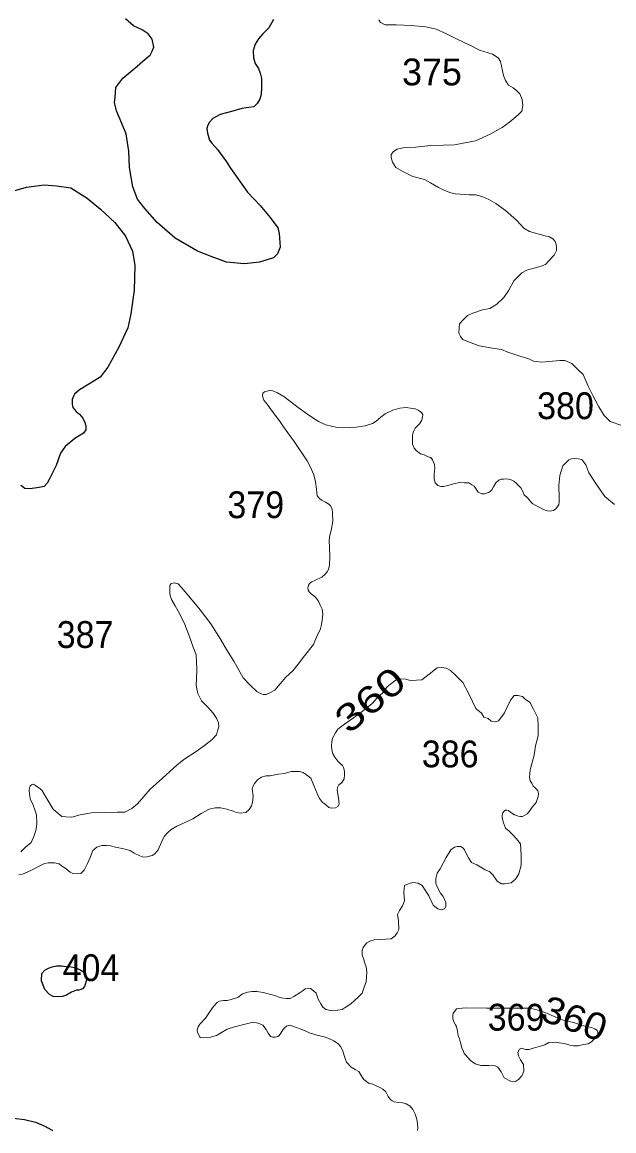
# Model space of a CAD drawing. Extents: x 445.4 to 500, y 8728.7 to 8784.
# Drawn here: x 478.95 to 482.49, y 8728.71 to 8735.33 of the extents above; entities that cross this region are included whole.
import ezdxf
from ezdxf.enums import TextEntityAlignment as Align

# ---------------------------------------------------------------- set-up
doc = ezdxf.new("R2010")
doc.units = 0
doc.header["$LTSCALE"] = 0.064
doc.layers.add('1', color=7, linetype='Continuous', lineweight=25)
doc.layers.add('2', color=7, linetype='Continuous', lineweight=13)
doc.layers.add('21', color=7, linetype='Continuous')
doc.layers.add('61', color=7, linetype='Continuous')

msp = doc.modelspace()

# ---------------------------------------------------------------- linework, layer by layer
at = {"layer": '1'}
for points in [[(480.4553, 8735.3481), (480.4282, 8735.2982), (480.3931, 8735.2632), (480.3661, 8735.2335), (480.3471, 8735.2012), (480.3336, 8735.1634), (480.3363, 8735.1203), (480.3471, 8735.0853), (480.3661, 8735.0556), (480.3769, 8735.0287), (480.385, 8734.9963), (480.385, 8734.9424), (480.3823, 8734.9006), (480.3742, 8734.8736), (480.358, 8734.8467), (480.3391, 8734.8278), (480.3094, 8734.8224), (480.2662, 8734.817), (480.2122, 8734.8008), (480.1366, 8734.782), (480.0934, 8734.7577), (480.0745, 8734.7362), (480.0637, 8734.7173), (480.0583, 8734.6984), (480.061, 8734.6688), (480.0745, 8734.6283), (480.088, 8734.6095), (480.1204, 8734.5717), (480.1744, 8734.4989), (480.1987, 8734.4612), (480.3012, 8734.3168), (480.3768, 8734.2386), (480.4362, 8734.1658), (480.4824, 8734.1051), (480.4905, 8734.07), (480.4932, 8734.0161), (480.4959, 8733.9891), (480.4797, 8733.9487), (480.4554, 8733.9245), (480.3717, 8733.9002), (480.2825, 8733.8894), (480.1745, 8733.9002), (480.0827, 8733.9325), (480.0017, 8733.9649), (479.869, 8734.0437), (479.7603, 8734.1361), (479.6879, 8734.2204), (479.6436, 8734.2766), (479.6154, 8734.3489), (479.5953, 8734.4654), (479.5913, 8734.5618), (479.5752, 8734.6662), (479.5189, 8734.8028), (479.5067, 8734.8537), (479.5107, 8734.8818), (479.5147, 8734.942), (479.555, 8734.9983), (479.6274, 8735.0585), (479.7038, 8735.1228), (479.7199, 8735.1348), (479.732, 8735.1589), (479.7401, 8735.183), (479.732, 8735.2312), (479.7079, 8735.2633), (479.6716, 8735.2874), (479.6193, 8735.3115), (479.571, 8735.3517)], [(478.8634, 8734.313), (478.9804, 8734.3472), (479.086, 8734.3614), (479.1602, 8734.3557), (479.2458, 8734.3443), (479.3428, 8734.2817), (479.4227, 8734.2162), (479.5083, 8734.1365), (479.571, 8734.0539), (479.6138, 8733.9656), (479.6281, 8733.8802), (479.6231, 8733.7332), (479.6031, 8733.5909), (479.586, 8733.5083), (479.5318, 8733.3915), (479.4661, 8733.2733), (479.4205, 8733.2135), (479.3634, 8733.1765), (479.2978, 8733.1367), (479.2664, 8733.111), (479.2607, 8733.0996), (479.2521, 8733.0797), (479.2521, 8733.0512), (479.2578, 8733.0313), (479.2778, 8733.0085), (479.2978, 8732.9914), (479.3177, 8732.9686), (479.3292, 8732.943), (479.3349, 8732.9231), (479.3349, 8732.8974), (479.3205, 8732.8787), (479.2692, 8732.8474), (479.2121, 8732.7989), (479.1836, 8732.7591), (479.1579, 8732.685), (479.118, 8732.6053), (479.1037, 8732.5797), (479.0866, 8732.5597), (479.0552, 8732.554), (479.001, 8732.5455), (478.9696, 8732.5483), (478.9468, 8732.5654)], [(478.6614, 8728.7126), (478.6828, 8728.7538), (478.7229, 8728.7791), (478.7734, 8728.7917), (478.8218, 8728.7896), (478.9019, 8728.7875), (478.9692, 8728.7812), (479.0345, 8728.7644), (479.0851, 8728.7433), (479.1335, 8728.716), (479.1368, 8728.7129)]]:
    msp.add_lwpolyline(points, dxfattribs=at)
msp.add_lwpolyline([(479.2487, 8729.5402), (479.2147, 8729.5202), (479.1931, 8729.514), (479.1653, 8729.5125), (479.139, 8729.5156), (479.1174, 8729.5264), (479.0896, 8729.5572), (479.0696, 8729.6081), (479.0726, 8729.6512), (479.0896, 8729.6713), (479.1112, 8729.6836), (479.1344, 8729.6928), (479.1591, 8729.6975), (479.19, 8729.6975), (479.2163, 8729.6944), (479.2472, 8729.6913), (479.275, 8729.6851), (479.3043, 8729.6728), (479.3259, 8729.6574), (479.3367, 8729.6389), (479.3414, 8729.6173), (479.3259, 8729.5742), (479.3151, 8729.5603), (479.295, 8729.5526), (479.2796, 8729.5526), (479.2688, 8729.548)], close=True, dxfattribs=at)
at = {"layer": '2'}
for points in [[(481.0861, 8735.3455), (481.0955, 8735.3314), (481.1237, 8735.3173), (481.1895, 8735.3173), (481.2788, 8735.3126), (481.3657, 8735.3056), (481.4268, 8735.2915), (481.4902, 8735.2634), (481.5536, 8735.2306), (481.6288, 8735.1954), (481.6875, 8735.1649), (481.7651, 8735.1415), (481.7979, 8735.1204), (481.812, 8735.0969), (481.8308, 8735.0149), (481.8426, 8734.9844), (481.8594, 8734.9554), (481.8875, 8734.9413), (481.9087, 8734.9226), (481.9275, 8734.9038), (481.9416, 8734.871), (481.9463, 8734.8358), (481.9392, 8734.8006), (481.9181, 8734.7795), (481.8664, 8734.735), (481.8218, 8734.7045), (481.7513, 8734.6633), (481.662, 8734.6234), (481.5892, 8734.6094), (481.5375, 8734.6), (481.4717, 8734.5976), (481.3966, 8734.5953), (481.305, 8734.5859), (481.2392, 8734.5836), (481.1941, 8734.5736), (481.173, 8734.5595), (481.1589, 8734.5431), (481.1589, 8734.5244), (481.1659, 8734.4962), (481.1871, 8734.4657), (481.2293, 8734.4399), (481.2881, 8734.4118), (481.3585, 8734.393), (481.3933, 8734.3729), (481.4419, 8734.3452), (481.479, 8734.3267), (481.5161, 8734.3128), (481.5439, 8734.3082), (481.625, 8734.3012), (481.6667, 8734.3012), (481.7061, 8734.2897), (481.7432, 8734.2735), (481.7849, 8734.2503), (481.8428, 8734.2087), (481.9077, 8734.1509), (481.9517, 8734.1023), (481.9852, 8734.0828), (482.0709, 8734.0597), (482.1057, 8734.0505), (482.1242, 8734.0389), (482.1381, 8734.0227), (482.1474, 8733.9973), (482.1474, 8733.9695), (482.1335, 8733.9417), (482.0987, 8733.9047), (482.0802, 8733.8862)], [(482.0802, 8733.8862), (482.0547, 8733.8747), (482.0107, 8733.8631), (481.9689, 8733.8515), (481.9388, 8733.8354), (481.9156, 8733.8122), (481.8923, 8733.7877), (481.8622, 8733.7322), (481.8321, 8733.6883), (481.7904, 8733.6489), (481.7487, 8733.6235), (481.7046, 8733.6142), (481.6467, 8733.5957), (481.6142, 8733.5819), (481.5864, 8733.5541), (481.5679, 8733.531), (481.5656, 8733.5079), (481.5633, 8733.4755), (481.5725, 8733.4547), (481.5864, 8733.4385), (481.6212, 8733.4246), (481.6838, 8733.3991), (481.7649, 8733.3853), (481.8182, 8733.3783), (481.8553, 8733.3621), (481.9273, 8733.3379), (481.9806, 8733.3217), (482.0084, 8733.3078), (482.0571, 8733.3032), (482.1011, 8733.3055), (482.166, 8733.3124), (482.1962, 8733.3124), (482.2379, 8733.2939), (482.2749, 8733.2592), (482.3051, 8733.2291), (482.3352, 8733.1598), (482.3628, 8733.1038), (482.3987, 8733.0353), (482.4315, 8732.9846), (482.4673, 8732.9489), (482.536, 8732.925)], [(481.7605, 8732.5407), (481.7509, 8732.531), (481.74, 8732.5238), (481.717, 8732.5166), (481.7001, 8732.5166), (481.6796, 8732.5262), (481.6675, 8732.5431), (481.6542, 8732.5612), (481.641, 8732.5709), (481.622, 8732.5825), (481.5944, 8732.5825), (481.5696, 8732.5839), (481.5317, 8732.5767), (481.5113, 8732.5694), (481.4895, 8732.5636), (481.472, 8732.5607), (481.456, 8732.5607), (481.437, 8732.5665), (481.4225, 8732.5825), (481.4166, 8732.6072), (481.4166, 8732.6363), (481.4196, 8732.6668), (481.4181, 8732.6915), (481.4064, 8732.7191), (481.3963, 8732.7337), (481.3802, 8732.738), (481.3555, 8732.7482), (481.3336, 8732.7555), (481.3089, 8732.7758), (481.2957, 8732.7889), (481.287, 8732.8136), (481.2855, 8732.8442), (481.2855, 8732.8674), (481.2914, 8732.8892), (481.303, 8732.9081), (481.3278, 8732.9337), (481.3409, 8732.9526), (481.3453, 8732.973), (481.3482, 8732.9904), (481.3409, 8733.002), (481.3205, 8733.0151), (481.303, 8733.0238), (481.2753, 8733.0282), (481.2491, 8733.0326), (481.2113, 8733.0282), (481.169, 8733.0166), (481.1224, 8732.9933), (481.0962, 8732.9744), (481.07, 8732.9497), (481.0481, 8732.9352), (481.0036, 8732.9221), (480.9497, 8732.9149), (480.874, 8732.9105), (480.8361, 8732.912), (480.7676, 8732.9279), (480.7239, 8732.9483), (480.6671, 8732.9861), (480.603, 8733.0326), (480.5185, 8733.098), (480.4802, 8733.12), (480.4525, 8733.1316), (480.4365, 8733.1345), (480.4176, 8733.1302), (480.403, 8733.1258), (480.3913, 8733.1171), (480.3899, 8733.104), (480.3928, 8733.0938), (480.3986, 8733.0749), (480.4176, 8733.0517), (480.4423, 8733.0182), (480.4671, 8732.9833), (480.4948, 8732.9455), (480.5166, 8732.9165), (480.5414, 8732.8801), (480.5792, 8732.8292), (480.6568, 8732.7136), (480.6757, 8732.6787), (480.6976, 8732.6293), (480.7063, 8732.5871), (480.7121, 8732.5443), (480.7165, 8732.505), (480.7281, 8732.4905), (480.7427, 8732.4788), (480.766, 8732.4672), (480.7864, 8732.4541), (480.7966, 8732.4454), (480.8068, 8732.4265), (480.8083, 8732.3989), (480.8097, 8732.3524), (480.801, 8732.2964), (480.7923, 8732.2703), (480.7893, 8732.2397), (480.7908, 8732.1918), (480.7923, 8732.1423), (480.7908, 8732.0906), (480.785, 8732.0644), (480.7762, 8732.0513), (480.7631, 8732.0339), (480.7442, 8732.0193), (480.702, 8731.999), (480.6845, 8731.9903)], [(482.4941, 8732.4533), (482.4344, 8732.501), (482.3897, 8732.5665), (482.3389, 8732.641), (482.321, 8732.6887), (482.2971, 8732.7214), (482.2762, 8732.7244), (482.2404, 8732.7274), (482.2195, 8732.7184), (482.1837, 8732.6827), (482.1658, 8732.6261), (482.1598, 8732.5665), (482.1628, 8732.492), (482.1623, 8732.4642), (482.1598, 8732.4525), (482.1523, 8732.4407), (482.143, 8732.4257), (482.1279, 8732.4165), (482.1162, 8732.4139), (482.1078, 8732.4131), (482.0935, 8732.4139), (482.0851, 8732.4173), (482.0683, 8732.4223), (482.0507, 8732.4324), (482.0239, 8732.4458), (482.0062, 8732.4558), (481.9928, 8732.4684), (481.9735, 8732.4918), (481.9534, 8732.5111), (481.943, 8732.5347), (481.9333, 8732.5527), (481.9104, 8732.5757), (481.8922, 8732.5913), (481.8765, 8732.5998), (481.8608, 8732.6046), (481.8439, 8732.6058), (481.8294, 8732.6046), (481.8161, 8732.6046), (481.8016, 8732.5986), (481.7835, 8732.5817), (481.7702, 8732.5576), (481.7605, 8732.5407)], [(480.6845, 8731.9903), (480.6714, 8731.9815), (480.6641, 8731.9714), (480.6612, 8731.9554), (480.6626, 8731.9408), (480.6699, 8731.9307), (480.6816, 8731.919), (480.7078, 8731.8987), (480.7253, 8731.8754), (480.7355, 8731.8521), (480.7471, 8731.8266), (480.7501, 8731.7976), (480.7471, 8731.7627), (480.7428, 8731.7365), (480.734, 8731.7045), (480.7165, 8731.6696), (480.6947, 8731.6173), (480.6408, 8731.5494), (480.6029, 8731.5), (480.5708, 8731.4593), (480.53, 8731.4215), (480.4965, 8731.3822), (480.463, 8731.343), (480.4339, 8731.327), (480.4121, 8731.3183), (480.396, 8731.3183), (480.3829, 8731.3226), (480.3567, 8731.3357), (480.3188, 8731.372), (480.2751, 8731.4171), (480.2198, 8731.5174), (480.1746, 8731.5858), (480.139, 8731.6486), (480.0807, 8731.7402), (480.0181, 8731.8231), (479.9597, 8731.8937), (479.9072, 8731.9577), (479.8854, 8731.978), (479.8621, 8731.9839), (479.8431, 8731.9795), (479.8358, 8731.9679), (479.8358, 8731.9475), (479.8373, 8731.917), (479.846, 8731.885), (479.8693, 8731.8472), (479.8941, 8731.8021), (479.9261, 8731.7353), (479.9495, 8731.6742), (479.9755, 8731.6008), (479.9929, 8731.5552), (479.9951, 8731.5117), (479.9972, 8731.4683), (479.9951, 8731.4074), (479.9929, 8731.377), (479.9972, 8731.351), (480.0038, 8731.3249), (480.0256, 8731.2801), (480.0626, 8731.2432), (480.0952, 8731.2062), (480.1148, 8731.1758), (480.1279, 8731.1497), (480.1301, 8731.1258), (480.1214, 8731.1019), (480.1148, 8731.078), (480.0887, 8731.0498), (480.043, 8731.0128), (479.9929, 8730.9781), (479.9211, 8730.9303), (479.8775, 8730.8955), (479.7727, 8730.8007), (479.7183, 8730.7529), (479.6443, 8730.666), (479.6094, 8730.6378), (479.5681, 8730.616), (479.5224, 8730.616), (479.444, 8730.6139), (479.3678, 8730.6117), (479.3003, 8730.5986), (479.2502, 8730.5856), (479.2154, 8730.5878), (479.1915, 8730.59), (479.1697, 8730.6073), (479.1392, 8730.6334), (479.0913, 8730.7138), (479.0709, 8730.7462), (479.0535, 8730.7614), (479.0347, 8730.7751), (479.0215, 8730.7818), (479.0108, 8730.7778), (479.0029, 8730.7711), (478.9989, 8730.7619), (478.9962, 8730.7433), (478.9975, 8730.7261), (479.0029, 8730.6942), (479.0201, 8730.6571), (479.0294, 8730.6293), (479.0401, 8730.5988), (479.0427, 8730.5477), (479.0374, 8730.5133), (479.0281, 8730.4801), (479.0082, 8730.435)], [(480.8401, 8730.9202), (480.8227, 8730.9429), (480.8097, 8730.9641), (480.8043, 8730.989), (480.8021, 8731.0118), (480.8043, 8731.0345), (480.8086, 8731.0572), (480.826, 8731.0897), (480.8401, 8731.1113), (480.88, 8731.1415), (480.9667, 8731.2021), (481.0036, 8731.2303), (481.0448, 8731.2649), (481.0752, 8731.2974), (481.1099, 8731.3277), (481.1359, 8731.3645), (481.1641, 8731.3883), (481.188, 8731.4056), (481.2075, 8731.4121), (481.2466, 8731.41), (481.2661, 8731.4035), (481.2856, 8731.4013), (481.3095, 8731.4035), (481.342, 8731.4056), (481.3854, 8731.4403), (481.4331, 8731.4771), (481.4592, 8731.4793), (481.4874, 8731.4749), (481.5134, 8731.4619), (481.5438, 8731.4338), (481.5871, 8731.3905), (481.6218, 8731.3255), (481.6457, 8731.2757), (481.6652, 8731.2346), (481.6978, 8731.2065), (481.7129, 8731.1826), (481.739, 8731.174), (481.7563, 8731.1588), (481.7824, 8731.1545), (481.7997, 8731.161), (481.8084, 8731.1697), (481.8366, 8731.2086), (481.8724, 8731.2847), (481.8941, 8731.3128), (481.9158, 8731.3128), (481.944, 8731.3064), (481.9613, 8731.289), (481.9895, 8731.2695), (481.996, 8731.2566), (482.0091, 8731.2306), (482.0221, 8731.2068), (482.0351, 8731.1786), (482.0373, 8731.1267), (482.0373, 8731.0704), (482.0221, 8731.0114), (482.0134, 8730.956), (481.9896, 8730.8673), (481.9878, 8730.8434), (481.9855, 8730.8249), (481.9902, 8730.8029), (481.9983, 8730.7878), (482.0064, 8730.7716), (482.018, 8730.7623), (482.0273, 8730.7519), (482.0343, 8730.7426), (482.0389, 8730.7275), (482.0378, 8730.7066), (482.0331, 8730.6962), (482.025, 8730.673), (482.0015, 8730.6455), (481.9858, 8730.622), (481.9714, 8730.6056), (481.9576, 8730.5971), (481.9438, 8730.5886), (481.932, 8730.5892), (481.9169, 8730.5905), (481.9091, 8730.5945), (481.896, 8730.6004), (481.873, 8730.6141), (481.8592, 8730.6246), (481.8494, 8730.6272), (481.8422, 8730.6265), (481.8343, 8730.6213), (481.8264, 8730.6115), (481.8225, 8730.5984), (481.8225, 8730.5807), (481.8307, 8730.5518), (481.8425, 8730.5207), (481.8629, 8730.5025), (481.8865, 8730.48), (481.9085, 8730.4561), (481.9322, 8730.4265), (481.9362, 8730.3594), (481.9362, 8730.2982), (481.9224, 8730.2469), (481.9026, 8730.2154), (481.8749, 8730.1937), (481.8354, 8730.1877), (481.8176, 8730.1877), (481.7919, 8730.2035), (481.7662, 8730.241)], [(478.9349, 8730.2421), (478.9562, 8730.246), (479.0053, 8730.2672), (479.0638, 8730.2977), (479.0877, 8730.3084), (479.1089, 8730.3123), (479.1488, 8730.3137), (479.1754, 8730.307), (479.19, 8730.2951), (479.2179, 8730.2765), (479.2405, 8730.258), (479.2577, 8730.25), (479.283, 8730.2474), (479.3055, 8730.25), (479.3241, 8730.2686), (479.3441, 8730.3097), (479.3613, 8730.3455), (479.3768, 8730.3855), (479.4007, 8730.4054), (479.43, 8730.4173), (479.4579, 8730.416), (479.4818, 8730.4147), (479.5123, 8730.4067), (479.5615, 8730.3961), (479.6, 8730.3855), (479.6239, 8730.3709), (479.6571, 8730.3537), (479.6771, 8730.347), (479.6983, 8730.3484), (479.7302, 8730.3563), (479.7475, 8730.3669), (479.7674, 8730.3908), (479.786, 8730.4359), (479.8019, 8730.4703), (479.8219, 8730.4929), (479.8444, 8730.5115), (479.879, 8730.5313), (479.9175, 8730.5499), (479.9746, 8730.5751), (480.0244, 8730.6077), (480.0722, 8730.6329), (480.1068, 8730.6409), (480.1413, 8730.6409), (480.1772, 8730.6342), (480.2144, 8730.621), (480.2343, 8730.613), (480.2569, 8730.6091), (480.2914, 8730.613), (480.3114, 8730.6303), (480.3247, 8730.6541), (480.33, 8730.6727), (480.3353, 8730.7112), (480.3286, 8730.7549), (480.334, 8730.7721), (480.3433, 8730.7867), (480.3605, 8730.8093), (480.3844, 8730.8252), (480.411, 8730.8331), (480.4362, 8730.8331), (480.4835, 8730.8416), (480.5207, 8730.8469), (480.5619, 8730.8589), (480.5858, 8730.8589), (480.611, 8730.8576), (480.6336, 8730.8523), (480.6522, 8730.8377), (480.6788, 8730.8191), (480.6974, 8730.774), (480.7173, 8730.7276), (480.7306, 8730.6971), (480.7492, 8730.6732), (480.7651, 8730.6626), (480.7866, 8730.644), (480.8026, 8730.64), (480.8265, 8730.6414), (480.8411, 8730.6493), (480.8477, 8730.6639), (480.8437, 8730.701), (480.8358, 8730.7461), (480.839, 8730.7632), (480.8455, 8730.7783), (480.8607, 8730.7881), (480.8661, 8730.7946), (480.878, 8730.8151), (480.8802, 8730.839), (480.8791, 8730.8606), (480.8737, 8730.8823), (480.8683, 8730.8942), (480.852, 8730.9072), (480.8401, 8730.9202)], [(479.0082, 8730.435), (478.9749, 8730.4059), (478.9471, 8730.3794)], [(481.7662, 8730.241), (481.7464, 8730.2608), (481.7207, 8730.2706), (481.6713, 8730.3002), (481.6396, 8730.314), (481.6199, 8730.3436), (481.606, 8730.3693), (481.5961, 8730.391), (481.5882, 8730.4009), (481.5744, 8730.4107), (481.5527, 8730.4107), (481.5368, 8730.4068), (481.5151, 8730.391), (481.4874, 8730.3456), (481.4518, 8730.2765), (481.434, 8730.2509), (481.4257, 8730.2188), (481.4257, 8730.1886), (481.4378, 8730.1615), (481.4529, 8730.1314), (481.468, 8730.1133), (481.477, 8730.0952), (481.4861, 8730.0741), (481.4861, 8730.053), (481.477, 8730.038), (481.4619, 8730.0319), (481.4378, 8730.038), (481.4106, 8730.0591), (481.3834, 8730.1163), (481.3442, 8730.1766), (481.32, 8730.1917), (481.2929, 8730.1947), (481.2717, 8730.1917), (481.2385, 8730.1766), (481.2355, 8730.1374), (481.2385, 8730.0862), (481.2264, 8730.056), (481.2083, 8730.0289), (481.1962, 8730.0048), (481.2023, 8729.9656), (481.2044, 8729.9156), (481.1954, 8729.8945), (481.1833, 8729.8764), (481.1592, 8729.8583), (481.0953, 8729.8555), (481.0576, 8729.8527), (481.031, 8729.8443), (481.0128, 8729.8345), (481.0016, 8729.822), (480.9918, 8729.808), (480.9862, 8729.7885), (480.9848, 8729.7619), (480.9932, 8729.741), (481.0002, 8729.7187), (481.0086, 8729.6921), (481.0128, 8729.6614), (481.0114, 8729.6307), (481.01, 8729.6028), (481.0002, 8729.5763), (480.9863, 8729.5349), (480.9607, 8729.5087), (480.918, 8729.4713), (480.8836, 8729.4484), (480.8659, 8729.437), (480.8398, 8729.4339), (480.8107, 8729.4297), (480.7961, 8729.4318), (480.7679, 8729.437), (480.7513, 8729.4515), (480.7377, 8729.4713), (480.7231, 8729.4983), (480.7117, 8729.5347), (480.695, 8729.5493), (480.6763, 8729.5628), (480.6627, 8729.5638), (480.645, 8729.5607), (480.6335, 8729.5503), (480.6148, 8729.5378), (480.5783, 8729.5139), (480.5554, 8729.5025), (480.5314, 8729.5025), (480.5023, 8729.5066), (480.4559, 8729.5224), (480.3945, 8729.539), (480.3559, 8729.5442), (480.3278, 8729.5442), (480.3007, 8729.5411), (480.2705, 8729.5297), (480.2424, 8729.5078), (480.2038, 8729.4964), (480.1799, 8729.4912), (480.1569, 8729.4912), (480.1325, 8729.4875), (480.1189, 8729.4789), (480.098, 8729.4556), (480.0783, 8729.4273), (480.05, 8729.3855), (480.0155, 8729.3499), (480.0061, 8729.3333), (479.9997, 8729.3152), (480.0018, 8729.3003)], [(480.0018, 8729.3003), (480.0114, 8729.2821), (480.0146, 8729.2747), (480.02, 8729.2704), (480.0371, 8729.2683), (480.0531, 8729.2704), (480.0788, 8729.2725), (480.1151, 8729.2821), (480.145, 8729.2992), (480.1792, 8729.3195), (480.222, 8729.3333), (480.2871, 8729.3493), (480.3192, 8729.3568), (480.3448, 8729.3589), (480.3641, 8729.3557), (480.3919, 8729.3429), (480.4122, 8729.3184), (480.425, 8729.2949), (480.4335, 8729.2821), (480.4378, 8729.2757), (480.4496, 8729.2715), (480.4592, 8729.2715), (480.4667, 8729.2725), (480.4816, 8729.2757), (480.4891, 8729.2821), (480.4998, 8729.296), (480.5115, 8729.3152), (480.5233, 8729.3301), (480.533, 8729.337), (480.5495, 8729.3439), (480.5599, 8729.3422), (480.5746, 8729.3352), (480.5868, 8729.3309), (480.5998, 8729.3266), (480.6189, 8729.3205), (480.6441, 8729.3101), (480.6753, 8729.2963), (480.6918, 8729.2911), (480.7152, 8729.2841), (480.7586, 8729.2729), (480.7899, 8729.2625), (480.8159, 8729.2495), (480.8419, 8729.233), (480.8584, 8729.214), (480.8697, 8729.1889), (480.8824, 8729.1499), (480.8922, 8729.1226), (480.9195, 8729.0934), (480.9429, 8729.0797), (480.9664, 8729.0661), (480.9859, 8729.0329), (480.9965, 8729.0188), (481.0114, 8729.0077), (481.0226, 8728.9978), (481.0486, 8728.9904), (481.0697, 8728.9817), (481.092, 8728.9718), (481.1093, 8728.9619), (481.1279, 8728.9446), (481.1403, 8728.9174), (481.1539, 8728.9001), (481.1639, 8728.8926), (481.1775, 8728.8865), (481.1998, 8728.8815), (481.2295, 8728.879), (481.2481, 8728.8728), (481.2717, 8728.8592), (481.289, 8728.8407), (481.3014, 8728.8122), (481.3126, 8728.7813), (481.3163, 8728.7553), (481.3175, 8728.7306), (481.3155, 8728.7142)]]:
    msp.add_lwpolyline(points, dxfattribs=at)
msp.add_lwpolyline([(481.6008, 8729.1683), (481.6332, 8729.133), (481.6598, 8729.1124), (481.6951, 8729.1036), (481.7423, 8729.1036), (481.7806, 8729.1006), (481.7954, 8729.0918), (481.816, 8729.0653), (481.8337, 8729.03), (481.872, 8729.0094), (481.9015, 8729.0065), (481.9192, 8729.0182), (481.9399, 8729.0418), (481.9516, 8729.0683), (481.9487, 8729.1095), (481.931, 8729.1359), (481.9192, 8729.1595), (481.9163, 8729.183), (481.9251, 8729.2007), (481.9369, 8729.2066), (481.9605, 8729.1977), (481.9841, 8729.1977), (482.0077, 8729.2066), (482.0448, 8729.2154), (482.0772, 8729.2267), (482.1015, 8729.2397), (482.1436, 8729.2413), (482.1631, 8729.238), (482.1939, 8729.2332), (482.2263, 8729.2235), (482.2473, 8729.2203), (482.2765, 8729.2203), (482.3073, 8729.2283), (482.3348, 8729.2316), (482.3559, 8729.2445), (482.3721, 8729.2607), (482.3818, 8729.2688), (482.3883, 8729.2801), (482.3931, 8729.2914), (482.3931, 8729.3011), (482.3899, 8729.3108), (482.3753, 8729.3221), (482.3559, 8729.3286), (482.2976, 8729.3415), (482.2506, 8729.3593), (482.1922, 8729.3723), (482.142, 8729.3917), (482.1015, 8729.4094), (482.0561, 8729.4272), (482.0205, 8729.4369), (481.9865, 8729.445), (481.9541, 8729.445), (481.8552, 8729.445), (481.7289, 8729.445), (481.6116, 8729.4467), (481.5824, 8729.4451), (481.563, 8729.4434), (481.55, 8729.4402), (481.5403, 8729.4289), (481.529, 8729.416), (481.5273, 8729.4014), (481.5273, 8729.382), (481.5338, 8729.3626), (481.5435, 8729.3448), (481.5484, 8729.3351), (481.5533, 8729.3173), (481.5597, 8729.2817), (481.5662, 8729.2623), (481.5727, 8729.2381), (481.5808, 8729.209), (481.5905, 8729.1863), (481.5954, 8729.175)], close=True, dxfattribs=at)

# ---------------------------------------------------------------- texts
at = {"layer": '21'}
msp.add_text('375', height=0.16, dxfattribs=at).set_placement((481.2241, 8734.9553))
at = {"layer": '21', "width": 0.95}
for s, p in [('380', (482.0309, 8732.9621)), ('379', (480.1803, 8732.371)), ('387', (479.1607, 8731.596)), ('386', (481.3419, 8730.8831)), ('404', (479.1958, 8729.6068)), ('369', (481.7358, 8729.311))]:
    msp.add_text(s, height=0.16, dxfattribs=at).set_placement(p)
at = {"layer": '61'}
for rotation, width, p in [(39.683, 1.3, (481.084, 8731.2248)), (340.189, 1.1, (482.2273, 8729.309))]:
    msp.add_text('360', height=0.16, rotation=rotation, dxfattribs=dict(at, width=width)).set_placement(p, align=Align.CENTER)

doc.saveas('drawing.dxf')
